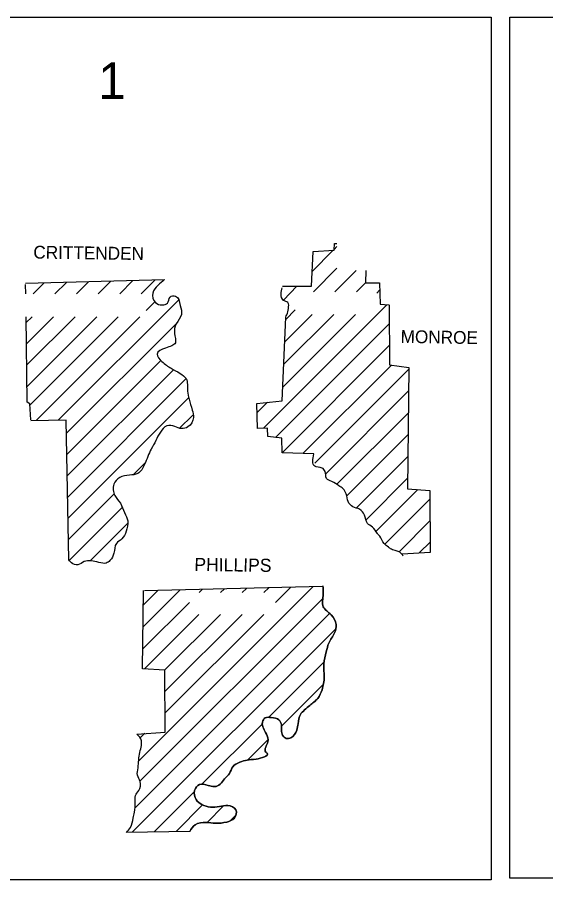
# Model space of a CAD drawing. Extents: x 23481 to 28196, y 1325020 to 1327623.
# Drawn here: x 27582.4 to 27755.3, y 1327340.9 to 1327623.3 of the extents above; entities that cross this region are included whole.
import ezdxf

# ---------------------------------------------------------------- set-up
doc = ezdxf.new("R2010")
doc.units = 0
doc.layers.add('S_ELECTRIC_UTILITIES_ANNOT', color=7, linetype='Continuous')

msp = doc.modelspace()

# ---------------------------------------------------------------- linework, layer by layer
at = {"layer": 'S_ELECTRIC_UTILITIES_ANNOT'}
msp.add_line((27638.84, 1327356.73), (27618.14, 1327356.43), dxfattribs=at)
for points in [[(27368.94, 1327623.33), (27737.44, 1327623.33), (27737.44, 1327340.93), (27368.94, 1327340.93)], [(28149.74, 1327341.43), (27743.64, 1327341.43), (27743.64, 1327623.33), (28149.74, 1327623.33)]]:
    msp.add_lwpolyline(points, close=True, dxfattribs=at)
for points in [[(27669.24, 1327535.23), (27678.64, 1327535.23), (27679.24, 1327546.63), (27686.14, 1327547.03), (27686.24, 1327549.23), (27686.94, 1327549.23)], [(27678.84, 1327540.03), (27685.74, 1327547.03)], [(27686.14, 1327547.33), (27686.94, 1327548.23)], [(27679.34, 1327533.43), (27686.94, 1327541.13)], [(27686.34, 1327533.43), (27693.34, 1327540.43)], [(27696.44, 1327540.43), (27696.34, 1327536.33), (27700.94, 1327536.33), (27701.14, 1327529.43), (27704.04, 1327529.13)], [(27585.14, 1327536.23), (27630.54, 1327537.43)], [(27615.94, 1327532.73), (27620.24, 1327537.13)], [(27622.94, 1327532.73), (27627.54, 1327537.33)], [(27585.24, 1327532.73), (27585.14, 1327535.83)], [(27587.64, 1327532.73), (27591.24, 1327536.33)], [(27594.74, 1327532.73), (27598.54, 1327536.53)], [(27601.74, 1327532.73), (27605.74, 1327536.73)], [(27608.84, 1327532.73), (27613.04, 1327536.93)], [(27669.54, 1327530.73), (27673.94, 1327535.23)], [(27693.44, 1327533.43), (27696.34, 1327536.33)], [(27700.04, 1327533.03), (27700.94, 1327533.93)], [(27595.84, 1327491.43), (27635.14, 1327530.73)], [(27624.64, 1327527.33), (27627.44, 1327530.13)], [(27662.94, 1327488.83), (27703.34, 1327529.13)], [(27704.14, 1327529.13), (27704.24, 1327509.53), (27710.54, 1327508.63), (27710.14, 1327468.93), (27717.44, 1327468.43), (27717.54, 1327448.13), (27708.34, 1327447.53)], [(27669.24, 1327502.13), (27693.14, 1327526.03)], [(27669.54, 1327509.63), (27686.04, 1327526.03)], [(27669.94, 1327517.03), (27678.94, 1327526.03)], [(27670.24, 1327524.33), (27673.34, 1327527.53)], [(27585.24, 1327523.33), (27587.24, 1327525.23)], [(27586.84, 1327491.53), (27586.54, 1327496.73), (27585.64, 1327497.33), (27585.34, 1327525.23)], [(27585.44, 1327509.43), (27601.34, 1327525.23)], [(27585.44, 1327516.43), (27594.24, 1327525.23)], [(27585.64, 1327502.43), (27608.44, 1327525.23)], [(27586.64, 1327496.43), (27615.44, 1327525.23)], [(27588.64, 1327491.33), (27622.54, 1327525.23)], [(27598.54, 1327487.13), (27634.44, 1327522.93)], [(27669.04, 1327480.73), (27668.94, 1327485.53), (27664.44, 1327486.03), (27664.34, 1327488.83), (27661.04, 1327488.73), (27660.84, 1327496.83), (27669.04, 1327497.73), (27670.24, 1327525.13)], [(27666.94, 1327485.73), (27704.14, 1327522.93)], [(27669.04, 1327480.73), (27704.14, 1327515.83)], [(27598.74, 1327480.23), (27629.44, 1327510.93)], [(27675.94, 1327480.63), (27704.84, 1327509.43)], [(27598.74, 1327473.23), (27633.54, 1327507.93)], [(27679.74, 1327477.33), (27710.44, 1327508.03)], [(27598.94, 1327466.23), (27637.64, 1327505.03)], [(27683.34, 1327473.83), (27710.34, 1327500.93)], [(27599.04, 1327459.33), (27638.54, 1327498.83)], [(27660.94, 1327493.93), (27664.34, 1327497.33)], [(27635.44, 1327488.63), (27639.84, 1327493.03)], [(27686.94, 1327470.43), (27710.34, 1327493.73)], [(27598.44, 1327491.43), (27586.84, 1327491.23)], [(27599.24, 1327445.63), (27598.44, 1327491.43)], [(27690.24, 1327466.63), (27710.24, 1327486.63)], [(27679.44, 1327480.43), (27669.04, 1327480.73)], [(27693.44, 1327462.73), (27710.14, 1327479.43)], [(27620.54, 1327473.73), (27624.34, 1327477.53)], [(27696.64, 1327458.93), (27710.14, 1327472.43)], [(27599.14, 1327452.33), (27614.14, 1327467.33)], [(27699.74, 1327454.93), (27713.54, 1327468.73)], [(27702.74, 1327450.83), (27717.44, 1327465.53)], [(27599.34, 1327445.43), (27616.84, 1327462.93)], [(27707.44, 1327448.43), (27717.54, 1327458.53)], [(27606.34, 1327445.43), (27618.64, 1327457.73)], [(27713.94, 1327447.93), (27717.64, 1327451.53)], [(27621.54, 1327388.63), (27630.84, 1327389.23), (27630.74, 1327409.53), (27623.44, 1327410.03), (27623.74, 1327435.63)], [(27622.14, 1327379.83), (27679.14, 1327436.83)], [(27623.64, 1327423.73), (27635.74, 1327435.83)], [(27623.64, 1327430.83), (27628.54, 1327435.73)], [(27624.04, 1327435.63), (27682.44, 1327437.03)], [(27641.94, 1327434.93), (27643.04, 1327436.03)], [(27648.94, 1327434.93), (27650.24, 1327436.23)], [(27656.04, 1327434.93), (27657.44, 1327436.33)], [(27663.14, 1327434.93), (27664.74, 1327436.53)], [(27666.94, 1327431.73), (27671.94, 1327436.73)], [(27622.64, 1327373.33), (27682.54, 1327433.13)], [(27623.64, 1327416.63), (27638.74, 1327431.73)], [(27620.94, 1327364.43), (27684.54, 1327428.13)], [(27624.04, 1327410.03), (27641.84, 1327427.83)], [(27630.64, 1327409.53), (27648.94, 1327427.83)], [(27630.84, 1327395.63), (27663.04, 1327427.83)], [(27630.84, 1327402.63), (27656.04, 1327427.83)], [(27620.04, 1327356.53), (27686.54, 1327423.03)], [(27664.64, 1327394.03), (27682.84, 1327412.23)], [(27668.74, 1327391.13), (27682.34, 1327404.63)], [(27642.74, 1327372.13), (27662.74, 1327392.13)], [(27622.64, 1327387.43), (27624.14, 1327388.93)], [(27657.84, 1327380.23), (27664.34, 1327386.63)], [(27627.24, 1327356.63), (27640.44, 1327369.83)], [(27634.44, 1327356.73), (27643.14, 1327365.53)], [(27644.54, 1327359.73), (27649.94, 1327365.13)], [(27652.04, 1327360.23), (27653.94, 1327362.13)]]:
    msp.add_lwpolyline(points, dxfattribs=at)
for points in [[(27630.54, 1327537.43), (27628.44, 1327535.53), (27626.74, 1327533.03), (27627.64, 1327529.93), (27629.84, 1327529.13), (27631.54, 1327529.73), (27632.44, 1327531.73), (27634.14, 1327532.03), (27635.74, 1327528.93)], [(27630.54, 1327537.43), (27628.44, 1327535.53), (27626.74, 1327533.03), (27627.64, 1327529.93), (27629.84, 1327529.13), (27631.54, 1327529.73), (27632.44, 1327531.73), (27634.14, 1327532.03), (27635.74, 1327528.93)], [(27670.24, 1327525.13), (27670.64, 1327525.93), (27671.14, 1327527.93), (27670.94, 1327529.93), (27669.54, 1327530.63), (27668.74, 1327532.73), (27669.14, 1327534.73)], [(27635.74, 1327528.93), (27636.14, 1327526.03), (27634.44, 1327522.93), (27633.84, 1327519.83), (27634.14, 1327516.73), (27630.94, 1327515.03), (27628.14, 1327513.03), (27629.74, 1327510.63), (27632.74, 1327508.43), (27635.74, 1327506.73), (27637.64, 1327505.03), (27638.14, 1327500.93), (27638.64, 1327498.33), (27639.64, 1327494.73), (27640.04, 1327492.23), (27638.24, 1327489.23), (27636.14, 1327488.63), (27633.94, 1327489.33), (27631.34, 1327489.53), (27629.24, 1327487.53), (27627.74, 1327484.73), (27626.24, 1327481.93), (27625.14, 1327479.53), (27624.04, 1327476.93), (27621.84, 1327473.93), (27619.14, 1327473.43), (27615.94, 1327472.63), (27614.04, 1327470.43), (27614.34, 1327466.73), (27616.14, 1327464.23), (27617.54, 1327461.13), (27618.54, 1327458.43), (27618.04, 1327455.03), (27616.64, 1327452.53), (27614.84, 1327451.03), (27614.04, 1327447.83), (27612.74, 1327445.43), (27611.54, 1327444.63), (27609.14, 1327444.83), (27606.54, 1327445.33), (27604.34, 1327445.13), (27602.24, 1327444.03), (27600.14, 1327444.73), (27599.24, 1327445.63)], [(27635.74, 1327528.93), (27636.14, 1327526.03), (27634.44, 1327522.93), (27633.84, 1327519.83), (27634.14, 1327516.73), (27630.94, 1327515.03), (27628.14, 1327513.03), (27629.74, 1327510.63), (27632.74, 1327508.43), (27635.74, 1327506.73), (27637.64, 1327505.03), (27638.14, 1327500.93), (27638.64, 1327498.33), (27639.64, 1327494.73), (27640.04, 1327492.23), (27638.24, 1327489.23), (27636.14, 1327488.63), (27633.94, 1327489.33), (27631.34, 1327489.53), (27629.24, 1327487.53), (27627.74, 1327484.73), (27626.24, 1327481.93), (27625.14, 1327479.53), (27624.04, 1327476.93), (27621.84, 1327473.93), (27619.14, 1327473.43), (27615.94, 1327472.63), (27614.04, 1327470.43), (27614.34, 1327466.73), (27616.14, 1327464.23), (27617.54, 1327461.13), (27618.54, 1327458.43), (27618.04, 1327455.03), (27616.64, 1327452.53), (27614.84, 1327451.03), (27614.04, 1327447.83), (27612.74, 1327445.43), (27611.54, 1327444.63), (27609.14, 1327444.83), (27606.54, 1327445.33), (27604.34, 1327445.13), (27602.24, 1327444.03), (27600.14, 1327444.73), (27599.24, 1327445.63)], [(27708.64, 1327446.93), (27708.44, 1327447.33), (27706.44, 1327448.63), (27704.84, 1327449.13), (27703.84, 1327449.83), (27702.44, 1327451.03), (27701.04, 1327453.43), (27700.24, 1327454.33), (27698.64, 1327456.43), (27697.04, 1327457.63), (27696.04, 1327460.33), (27694.44, 1327462.23), (27692.24, 1327463.03), (27690.64, 1327464.73), (27690.04, 1327467.33), (27689.04, 1327468.93), (27687.64, 1327469.93), (27685.34, 1327471.33), (27683.64, 1327472.33), (27683.14, 1327474.63), (27682.14, 1327475.73), (27679.74, 1327476.33), (27679.44, 1327480.43)], [(27682.44, 1327437.13), (27682.54, 1327434.43), (27682.54, 1327430.33), (27685.14, 1327427.63), (27686.74, 1327424.53), (27686.24, 1327421.73), (27684.34, 1327418.43), (27683.54, 1327415.53), (27682.74, 1327411.63), (27682.84, 1327407.33), (27682.14, 1327403.13), (27680.74, 1327400.33), (27678.14, 1327398.03), (27676.44, 1327396.53), (27675.04, 1327395.03), (27674.34, 1327392.03), (27673.84, 1327389.93), (27671.94, 1327387.43), (27670.44, 1327387.23), (27669.24, 1327388.23), (27668.84, 1327389.93), (27668.84, 1327391.63), (27668.04, 1327393.33), (27665.54, 1327394.03), (27663.54, 1327393.93), (27662.64, 1327392.53), (27663.94, 1327388.63), (27664.44, 1327386.13), (27663.74, 1327382.73), (27664.14, 1327382.33), (27660.54, 1327380.43), (27657.64, 1327380.13), (27655.24, 1327379.43), (27652.94, 1327377.93), (27651.84, 1327375.73), (27650.24, 1327373.93), (27648.84, 1327372.23), (27646.94, 1327371.43), (27644.84, 1327371.83), (27642.04, 1327372.13), (27640.44, 1327370.13), (27640.94, 1327367.23), (27642.84, 1327365.53), (27645.64, 1327364.73), (27648.54, 1327364.93), (27651.34, 1327365.23), (27653.94, 1327363.83), (27653.44, 1327361.13), (27650.94, 1327359.83), (27647.24, 1327359.43), (27644.24, 1327359.73), (27640.64, 1327358.93), (27638.84, 1327356.73)], [(27682.44, 1327437.13), (27682.54, 1327434.43), (27682.54, 1327430.33), (27685.14, 1327427.63), (27686.74, 1327424.53), (27686.24, 1327421.73), (27684.34, 1327418.43), (27683.54, 1327415.53), (27682.74, 1327411.63), (27682.84, 1327407.33), (27682.14, 1327403.13), (27680.74, 1327400.33), (27678.14, 1327398.03), (27676.44, 1327396.53), (27675.04, 1327395.03), (27674.34, 1327392.03), (27673.84, 1327389.93), (27671.94, 1327387.43), (27670.44, 1327387.23), (27669.24, 1327388.23), (27668.84, 1327389.93), (27668.84, 1327391.63), (27668.04, 1327393.33), (27665.54, 1327394.03), (27663.54, 1327393.93), (27662.64, 1327392.53), (27663.94, 1327388.63), (27664.44, 1327386.13), (27663.74, 1327382.73), (27664.14, 1327382.33), (27660.54, 1327380.43), (27657.64, 1327380.13), (27655.24, 1327379.43), (27652.94, 1327377.93), (27651.84, 1327375.73), (27650.24, 1327373.93), (27648.84, 1327372.23), (27646.94, 1327371.43), (27644.84, 1327371.83), (27642.04, 1327372.13), (27640.44, 1327370.13), (27640.94, 1327367.23), (27642.84, 1327365.53), (27645.64, 1327364.73), (27648.54, 1327364.93), (27651.34, 1327365.23), (27653.94, 1327363.83), (27653.44, 1327361.13), (27650.94, 1327359.83), (27647.24, 1327359.43), (27644.24, 1327359.73), (27640.64, 1327358.93), (27638.84, 1327356.73)], [(27638.84, 1327356.73), (27640.64, 1327358.93), (27644.24, 1327359.73), (27647.24, 1327359.43), (27650.94, 1327359.83), (27653.44, 1327361.13), (27653.94, 1327363.83), (27651.34, 1327365.23), (27648.54, 1327364.93), (27645.64, 1327364.73), (27642.84, 1327365.53), (27640.94, 1327367.23), (27640.44, 1327370.13), (27642.04, 1327372.13), (27644.84, 1327371.83), (27646.94, 1327371.43), (27648.84, 1327372.23), (27650.24, 1327373.93), (27651.84, 1327375.73), (27652.94, 1327377.93), (27655.24, 1327379.43), (27657.64, 1327380.13), (27660.54, 1327380.43), (27664.14, 1327382.33), (27663.74, 1327382.73), (27664.44, 1327386.13), (27663.94, 1327388.63), (27662.64, 1327392.53), (27663.54, 1327393.93), (27665.54, 1327394.03), (27668.04, 1327393.33), (27668.84, 1327391.63), (27668.84, 1327389.93), (27669.24, 1327388.23), (27670.44, 1327387.23), (27671.94, 1327387.43), (27673.84, 1327389.93), (27674.34, 1327392.03), (27675.04, 1327395.03), (27676.44, 1327396.53), (27678.14, 1327398.03), (27680.74, 1327400.33), (27682.14, 1327403.13), (27682.84, 1327407.33), (27682.74, 1327411.63), (27683.54, 1327415.53), (27684.34, 1327418.43), (27686.24, 1327421.73), (27686.74, 1327424.53), (27685.14, 1327427.63), (27682.54, 1327430.33), (27682.54, 1327434.43), (27682.44, 1327437.13)], [(27682.44, 1327437.13), (27682.54, 1327434.43), (27682.54, 1327430.33), (27685.14, 1327427.63), (27686.74, 1327424.53), (27686.24, 1327421.73), (27684.34, 1327418.43), (27683.54, 1327415.53), (27682.74, 1327411.63), (27682.84, 1327407.33), (27682.14, 1327403.13), (27680.74, 1327400.33), (27678.14, 1327398.03), (27676.44, 1327396.53), (27675.04, 1327395.03), (27674.34, 1327392.03), (27673.84, 1327389.93), (27671.94, 1327387.43), (27670.44, 1327387.23), (27669.24, 1327388.23), (27668.84, 1327389.93), (27668.84, 1327391.63), (27668.04, 1327393.33), (27665.54, 1327394.03), (27663.54, 1327393.93), (27662.64, 1327392.53), (27663.94, 1327388.63), (27664.44, 1327386.13), (27663.74, 1327382.73), (27664.14, 1327382.33), (27660.54, 1327380.43), (27657.64, 1327380.13), (27655.24, 1327379.43), (27652.94, 1327377.93), (27651.84, 1327375.73), (27650.24, 1327373.93), (27648.84, 1327372.23), (27646.94, 1327371.43), (27644.84, 1327371.83), (27642.04, 1327372.13), (27640.44, 1327370.13), (27640.94, 1327367.23), (27642.84, 1327365.53), (27645.64, 1327364.73), (27648.54, 1327364.93), (27651.34, 1327365.23), (27653.94, 1327363.83), (27653.44, 1327361.13), (27650.94, 1327359.83), (27647.24, 1327359.43), (27644.24, 1327359.73), (27640.64, 1327358.93), (27638.84, 1327356.73)], [(27682.44, 1327437.13), (27682.54, 1327434.43), (27682.54, 1327430.33), (27685.14, 1327427.63), (27686.74, 1327424.53), (27686.24, 1327421.73), (27684.34, 1327418.43), (27683.54, 1327415.53), (27682.74, 1327411.63), (27682.84, 1327407.33), (27682.14, 1327403.13), (27680.74, 1327400.33), (27678.14, 1327398.03), (27676.44, 1327396.53), (27675.04, 1327395.03), (27674.34, 1327392.03), (27673.84, 1327389.93), (27671.94, 1327387.43), (27670.44, 1327387.23), (27669.24, 1327388.23), (27668.84, 1327389.93), (27668.84, 1327391.63), (27668.04, 1327393.33), (27665.54, 1327394.03), (27663.54, 1327393.93), (27662.64, 1327392.53), (27663.94, 1327388.63), (27664.44, 1327386.13), (27663.74, 1327382.73), (27664.14, 1327382.33), (27660.54, 1327380.43), (27657.64, 1327380.13), (27655.24, 1327379.43), (27652.94, 1327377.93), (27651.84, 1327375.73), (27650.24, 1327373.93), (27648.84, 1327372.23), (27646.94, 1327371.43), (27644.84, 1327371.83), (27642.04, 1327372.13), (27640.44, 1327370.13), (27640.94, 1327367.23), (27642.84, 1327365.53), (27645.64, 1327364.73), (27648.54, 1327364.93), (27651.34, 1327365.23), (27653.94, 1327363.83), (27653.44, 1327361.13), (27650.94, 1327359.83), (27647.24, 1327359.43), (27644.24, 1327359.73), (27640.64, 1327358.93), (27638.84, 1327356.73)], [(27618.14, 1327356.43), (27619.44, 1327358.03), (27620.34, 1327361.13), (27620.74, 1327363.03), (27621.04, 1327366.33), (27621.14, 1327368.53), (27622.14, 1327370.13), (27622.64, 1327373.13), (27621.74, 1327375.13), (27621.94, 1327377.53), (27622.14, 1327380.23), (27622.54, 1327382.63), (27623.04, 1327384.93), (27623.04, 1327386.43), (27621.54, 1327388.63)]]:
    msp.add_spline(points, degree=3, dxfattribs=at)

# ---------------------------------------------------------------- texts
msp.add_text('1', height=12, dxfattribs=at).set_placement((27608.94, 1327596.53))
for s, height, rotation, p in [('CRITTENDEN', 4.201, 359.213, (27587.64, 1327544.33)), ('MONROE', 4.199, 359.0331, (27707.84, 1327516.73)), ('PHILLIPS', 4.3, 359.3179, (27640.34, 1327442.03))]:
    msp.add_text(s, height=height, rotation=rotation, dxfattribs=at).set_placement(p)

doc.saveas('drawing.dxf')
